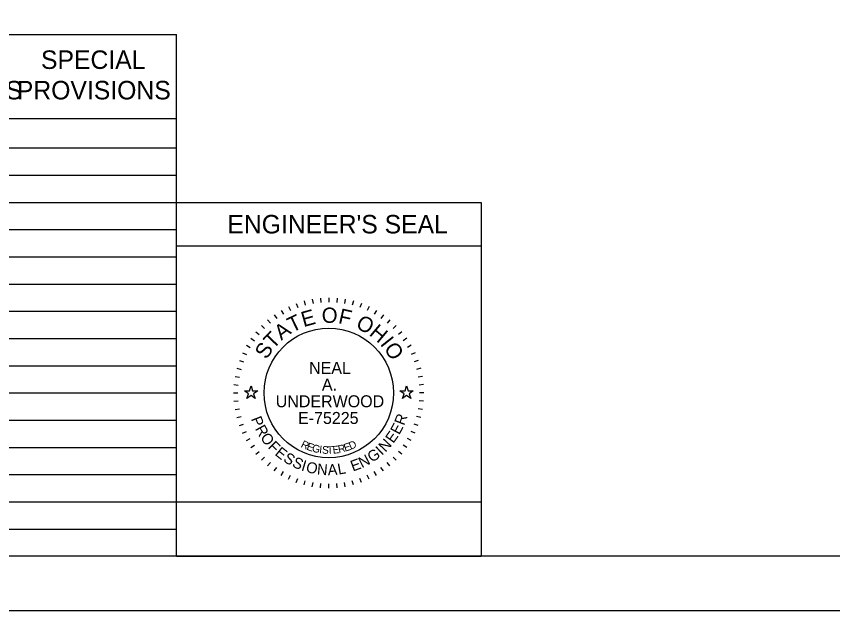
# Model space of a CAD drawing. Extents: x 0 to 34, y 0 to 22.
# Drawn here: x 22.13 to 29.63, y 0 to 5.46 of the extents above; entities that cross this region are included whole.
import ezdxf

# ---------------------------------------------------------------- set-up
doc = ezdxf.new("R2010")
doc.units = 0
for name, color, linetype in [('Default', 7, 'Continuous'), ('SH_Border', 7, 'Continuous'), ('SH_Cut_Line', 7, 'Continuous'), ('SH_Data', 7, 'Continuous'), ('SH_Text', 7, 'Continuous')]:
    doc.layers.add(name, color=color, linetype=linetype)

msp = doc.modelspace()

# ---------------------------------------------------------------- linework, layer by layer
at = {"layer": 'Default'}
for points in [[(24.2236, 2.02), (24.2705, 2.02), (24.285, 2.0645), (24.2995, 2.02), (24.3464, 2.02), (24.3085, 1.9924), (24.323, 1.9478), (24.285, 1.9754), (24.247, 1.9478), (24.2615, 1.9924)], [(25.6536, 2.02), (25.7005, 2.02), (25.715, 2.0645), (25.7295, 2.02), (25.7764, 2.02), (25.7385, 1.9924), (25.753, 1.9478), (25.715, 1.9754), (25.677, 1.9478), (25.6915, 1.9924)]]:
    msp.add_lwpolyline(points, close=True, dxfattribs=at)
at = {"layer": 'SH_Border'}
msp.add_lwpolyline([(1.5, 21.5), (33.5, 21.5), (33.5, 0.5), (1.5, 0.5)], close=True, dxfattribs=at)
at = {"layer": 'SH_Cut_Line'}
msp.add_lwpolyline([(0, 0), (34, 0), (34, 22), (0, 22)], close=True, dxfattribs=at)
at = {"layer": 'SH_Data'}
for p, q in [((10.15, 5.2917), (23.6, 5.2917)), ((23.6, 0.5), (23.6, 5.2917)), ((10.15, 4.5209), (23.6, 4.5209)), ((10.15, 4.25), (23.6, 4.25)), ((10.15, 4), (23.6, 4)), ((10.15, 3.75), (23.6, 3.75)), ((23.6, 0.5), (23.6, 3.75)), ((23.6, 0.5), (23.6, 3.75)), ((23.6, 3.75), (26.4, 3.75)), ((26.4, 3.75), (26.4, 0.5)), ((10.15, 3.5), (23.6, 3.5)), ((23.6, 3.35), (26.4, 3.35)), ((10.15, 3.25), (23.6, 3.25)), ((10.15, 3), (23.6, 3)), ((24.8481, 2.8617), (24.855, 2.8223)), ((24.9237, 2.8717), (24.9272, 2.8318)), ((25, 2.875), (25, 2.835)), ((25.0763, 2.8717), (25.0728, 2.8318)), ((25.1519, 2.8617), (25.145, 2.8223)), ((24.6302, 2.793), (24.6471, 2.7568)), ((24.7007, 2.8222), (24.7144, 2.7846)), ((24.7735, 2.8452), (24.7839, 2.8065)), ((25.2265, 2.8452), (25.2161, 2.8065)), ((25.2993, 2.8222), (25.2856, 2.7846)), ((25.3698, 2.793), (25.3529, 2.7568)), ((10.15, 2.75), (23.6, 2.75)), ((24.4981, 2.7168), (24.5211, 2.684)), ((24.5625, 2.7578), (24.5825, 2.7231)), ((25.4375, 2.7578), (25.4175, 2.7231)), ((25.5019, 2.7168), (25.4789, 2.684)), ((24.4376, 2.6703), (24.4633, 2.6396)), ((25.5624, 2.6703), (25.5367, 2.6396)), ((24.3297, 2.5624), (24.3604, 2.5367)), ((24.3813, 2.6187), (24.4096, 2.5904)), ((25.6187, 2.6187), (25.5904, 2.5904)), ((25.6703, 2.5624), (25.6396, 2.5367)), ((10.15, 2.5), (23.6, 2.5)), ((24.2832, 2.5019), (24.316, 2.4789)), ((25.7168, 2.5019), (25.684, 2.4789)), ((24.2422, 2.4375), (24.2769, 2.4175)), ((25.7578, 2.4375), (25.7231, 2.4175)), ((24.207, 2.3698), (24.2432, 2.3529)), ((25.793, 2.3698), (25.7568, 2.3529)), ((24.1778, 2.2993), (24.2154, 2.2856)), ((25.8222, 2.2993), (25.7846, 2.2856)), ((10.15, 2.25), (23.6, 2.25)), ((24.1548, 2.2265), (24.1935, 2.2161)), ((25.8452, 2.2265), (25.8065, 2.2161)), ((24.1383, 2.1519), (24.1777, 2.145)), ((25.8617, 2.1519), (25.8223, 2.145)), ((24.1283, 2.0763), (24.1682, 2.0728)), ((25.8717, 2.0763), (25.8318, 2.0728)), ((10.15, 2), (23.6, 2)), ((24.125, 2), (24.165, 2)), ((25.875, 2), (25.835, 2)), ((24.1283, 1.9237), (24.1682, 1.9272)), ((25.8717, 1.9237), (25.8318, 1.9272)), ((24.1383, 1.8481), (24.1777, 1.855)), ((25.8617, 1.8481), (25.8223, 1.855)), ((10.15, 1.75), (23.6, 1.75)), ((24.1548, 1.7735), (24.1935, 1.7839)), ((25.8452, 1.7735), (25.8065, 1.7839)), ((24.1778, 1.7007), (24.2154, 1.7144)), ((25.8222, 1.7007), (25.7846, 1.7144)), ((24.207, 1.6302), (24.2432, 1.6471)), ((24.2422, 1.5625), (24.2769, 1.5825)), ((25.7578, 1.5625), (25.7231, 1.5825)), ((25.793, 1.6302), (25.7568, 1.6471)), ((24.2832, 1.4981), (24.316, 1.5211)), ((25.7168, 1.4981), (25.684, 1.5211)), ((10.15, 1.5), (23.6, 1.5)), ((24.3297, 1.4376), (24.3604, 1.4633)), ((25.6703, 1.4376), (25.6396, 1.4633)), ((24.3813, 1.3813), (24.4096, 1.4096)), ((24.4376, 1.3297), (24.4633, 1.3604)), ((25.5624, 1.3297), (25.5367, 1.3604)), ((25.6187, 1.3813), (25.5904, 1.4096)), ((24.4981, 1.2832), (24.5211, 1.316)), ((24.5625, 1.2422), (24.5825, 1.2769)), ((25.4375, 1.2422), (25.4175, 1.2769)), ((25.5019, 1.2832), (25.4789, 1.316)), ((10.15, 1.25), (23.6, 1.25)), ((24.6302, 1.207), (24.6471, 1.2432)), ((24.7007, 1.1778), (24.7144, 1.2154)), ((25.2993, 1.1778), (25.2856, 1.2154)), ((25.3698, 1.207), (25.3529, 1.2432)), ((24.7735, 1.1548), (24.7839, 1.1935)), ((24.8481, 1.1383), (24.855, 1.1777)), ((24.9237, 1.1283), (24.9272, 1.1682)), ((25, 1.125), (25, 1.165)), ((25.0763, 1.1283), (25.0728, 1.1682)), ((25.1519, 1.1383), (25.145, 1.1777)), ((25.2265, 1.1548), (25.2161, 1.1935)), ((10.15, 1), (23.6, 1)), ((10.15, 0.75), (23.6, 0.75)), ((23.6, 0.5), (26.4, 0.5)), ((23.6, 0.5), (26.4, 0.5))]:
    msp.add_line(p, q, dxfattribs=at)
msp.add_lwpolyline([(23.6, 0.5), (23.6, 1), (26.4, 1), (26.4, 0.5)], close=True, dxfattribs=at)
msp.add_circle((25, 2), 0.595, dxfattribs=at)

# ---------------------------------------------------------------- texts
for s, height, p in [("ENGINEER'S SEAL", 0.17, (24.0676, 3.465)), ('NEAL', 0.11, (24.8188, 2.1749)), ('A.', 0.11, (24.9369, 2.0216)), ('UNDERWOOD', 0.11, (24.5122, 1.8684)), ('E-75225', 0.11, (24.7173, 1.7151))]:
    msp.add_text(s, height=height, dxfattribs=at).set_placement(p)
for s, height, rotation, p in [('O', 0.14, 359.78119, (24.9347, 2.6443)), ('T', 0.14, 25.71674, (24.6616, 2.5518)), ('E', 0.14, 15.75706, (24.7684, 2.6038)), ('F', 0.14, 347.43619, (25.0811, 2.6417)), ('O', 0.14, 332.25863, (25.2398, 2.6015)), ('A', 0.14, 36.47472, (24.5634, 2.4781)), ('H', 0.14, 319.91363, (25.3632, 2.5361)), ('T', 0.14, 46.4344, (24.4883, 2.3964)), ('I', 0.14, 308.36695, (25.4665, 2.4483)), ('S', 0.14, 57.19238, (24.4281, 2.3014)), ('O', 0.14, 303.14906, (25.5021, 2.4089)), ('R', 0.1, 69.23216, (25.6919, 1.6954)), ('P', 0.1, 291.49398, (24.2823, 1.7621)), ('E', 0.1, 61.99508, (25.6476, 1.6098)), ('R', 0.1, 298.73106, (24.319, 1.6717)), ('E', 0.1, 54.75801, (25.5933, 1.5314)), ('O', 0.1, 306.46664, (24.3655, 1.5883)), ('N', 0.1, 47.02243, (25.5202, 1.4508)), ('F', 0.1, 314.7068, (24.4343, 1.4983)), ('E', 0.1, 321.43929, (24.4978, 1.4348)), ('R', 0.07, 334.48695, (24.7375, 1.5051)), ('E', 0.07, 341.03996, (24.7906, 1.4801)), ('G', 0.07, 347.47515, (24.8414, 1.4618)), ('I', 0.07, 353.78581, (24.9091, 1.4468)), ('S', 0.07, 356.89262, (24.9358, 1.4429)), ('T', 0.07, 3.00609, (24.9857, 1.4387)), ('E', 0.07, 6.01169, (25.0389, 1.4412)), ('R', 0.07, 11.91844, (25.0925, 1.4474)), ('E', 0.07, 17.68363, (25.1498, 1.4602)), ('D', 0.07, 23.30524, (25.201, 1.477)), ('I', 0.1, 43.28703, (25.4868, 1.4214)), ('S', 0.1, 328.67637, (24.5743, 1.3752)), ('N', 0.1, 27.31129, (25.3045, 1.3075)), ('G', 0.1, 35.04687, (25.3981, 1.357)), ('S', 0.1, 335.91345, (24.6564, 1.3266)), ('I', 0.1, 343.15053, (24.7406, 1.2897)), ('O', 0.1, 346.88592, (24.7839, 1.2751)), ('L', 0.1, 10.09874, (25.0894, 1.249)), ('E', 0.1, 20.07421, (25.2212, 1.277)), ('N', 0.1, 355.12608, (24.8888, 1.2517)), ('A', 0.1, 2.86166, (24.9923, 1.2437))]:
    msp.add_text(s, height=height, rotation=rotation, dxfattribs=at).set_placement(p)
at = {"layer": 'SH_Text'}
for s, p in [('SPECIAL', (22.3542, 4.9763)), ('SPECIFICATIONS', (20.2871, 4.6963)), ('PROVISIONS', (22.1323, 4.6963))]:
    msp.add_text(s, height=0.17, dxfattribs=at).set_placement(p)

doc.saveas('drawing.dxf')
